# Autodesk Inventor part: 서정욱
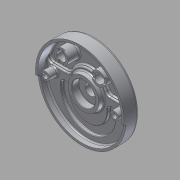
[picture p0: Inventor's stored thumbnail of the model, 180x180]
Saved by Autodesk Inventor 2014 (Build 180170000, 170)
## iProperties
Created: 2015-05
Part Number: 서정욱
Material: 알루미늄 6061
Document SubType Name: Modeling
Designer: USER
Density: 2.71 g/cm^3
Appearance: 알루미늄 - 평지
Mass: 1116.19 g
Surface Area: 1056.09 cm^2
Volume: 411.879 cm^3
Author: USER
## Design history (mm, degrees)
sketch "스케치1"
  geometry: C1 r 95 at (0, 0); 1 further point
  constraints: 1 centre point, 1 coincident
  dimensions: "d0" = 190 diameter of C1
extrude "돌출1" new body sketch "스케치1" distance "d1" = 32; taper "d2" = 0 deg
sketch "스케치2"
  geometry: L1 (0, 0)-(94.638, -8.28); L2 (-95, 0)-(95, 0); L3 (0, 0)-(-94.638, -8.28); A1 r 95 centre (0, 0) between (94.638, -8.28) and (-95, 0) reference
  constraints: 6 end point, 4 point on circle, 1 coincident, 1 horizontal, 1 midpoint
  dimensions: "d4" = 5 deg angle of L1 L2; "d5" = 5 deg angle of L3 L2
extrude "돌출2" cut sketch "스케치2" distance "d7" = 5; taper "d8" = 0 deg
sketch "스케치3"
  geometry: L1 (-89.196, 12)-(-40.249, 12); L2 (40.249, 12)-(89.196, 12); A1 r 95 centre (0, 0) between (94.638, -8.28) and (-94.638, -8.28) reference; A2 r 90 centre (0, 0) between (89.196, 12) and (-89.196, 12); A3 r 42 centre (0, 0) between (40.249, 12) and (-40.249, 12); 1 further point
  constraints: 4 end point, 4 point on circle, 2 centre point, 2 coincident, 2 horizontal
  dimensions: "d9" = 180 diameter of A2; "d10" = 84 diameter of A3; "d12" = 12 distance from line of point (0, 0) L2; "d13" = 12 distance from line of point (0, 0) L1
extrude "돌출3" cut sketch "스케치3" distance "d14" = 25; taper "d15" = 0 deg
fillet "모깎기1" dims "d16" = 10
sketch "스케치4"
  geometry: L1 (76.916, 12)-(47.117, 12) reference; L2 (-47.117, 12)-(-76.916, 12) reference; C1 r 90 at (0, 0); A1 r 10 centre (47.117, 22) between (38.056, 17.769) and (47.117, 12) reference; A2 r 42 centre (0, 0) between (38.056, 17.769) and (-38.056, 17.769) reference; A3 r 10 centre (-47.117, 22) between (-47.117, 12) and (-38.056, 17.769) reference; A4 r 10 centre (-76.916, 22) between (-86.53, 24.75) and (-76.916, 12) reference; A5 r 90 centre (0, 0) between (86.53, 24.75) and (-86.53, 24.75) reference; A6 r 10 centre (76.916, 22) between (76.916, 12) and (86.53, 24.75) reference; A7 r 95 centre (0, 0) between (94.638, -8.28) and (-94.638, -8.28) reference
  constraints: 1 centre point, 1 coincident
  dimensions: "d17" = 180 diameter of C1
extrude "돌출4" cut sketch "스케치4" distance "d18" = 18; taper "d19" = 0 deg
sketch "스케치16"
  geometry: C1 r 95 at (0, 0) reference; C2 r 25 at (0, 0)
  constraints: 1 centre point, 1 coincident
  dimensions: "d98" = 50 diameter of C2
extrude "돌출13" join sketch "스케치16" distance "d99" = 12; taper "d100" = -15 deg
sketch "스케치17"
  geometry: C1 r 35 at (0, 0); A1 r 42 centre (0, 0) between (38.056, 17.769) and (-38.056, 17.769) reference
  constraints: 1 centre point, 1 coincident
  dimensions: "d101" = 70 diameter of C1
extrude "돌출14" join sketch "스케치17" distance "d102" = 10; taper "d103" = -10 deg
hole "구멍3" diameter "d106" = 23; stored, may be unused: countersink angle "d110" = 90 deg, drill point angle "d112" = 118 deg; dims "d104" = 10, "d105" = 10, "d107" = 6, "d108" = 50, "d109" = 15, "d111" = 8
sketch "스케치18"
  geometry: C1 r 25 at (0, 0) reference; C2 r 9 at (74, 0)
  constraints: 1 centre point, 1 horizontal alignment
  dimensions: "d113" = 18 diameter of C2; "d114" = 74 distance of C1.centre C2.centre
extrude "돌출15" join sketch "스케치18" distance "d115" = 32; taper "d116" = 0 deg
hole "구멍4" sketch "스케치18" diameter "d117" = 11; stored, may be unused: countersink angle "d121" = 90 deg, drill point angle "d123" = 118 deg; dims "d118" = 6, "d119" = 18, "d120" = 11, "d122" = 8
sketch "스케치19"
  geometry: C1 r 9 at (74, 0) reference; C2 r 25 at (0, 0) reference; C3 r 15 at (40, -52)
  constraints: 1 centre point
  dimensions: "d124" = 30 diameter of C3; "d125" = 52 vertical distance of C1.centre C3.centre; "d126" = 40 horizontal distance of C2.centre C3.centre
extrude "돌출16" join sketch "스케치19" distance "d127" = 32; taper "d128" = 0 deg
hole "구멍5" diameter "d131" = 20; stored, may be unused: countersink angle "d135" = 90 deg, drill point angle "d137" = 118 deg; dims "d129" = 10, "d130" = 10, "d132" = 6, "d133" = 10, "d134" = 11, "d136" = 8
sketch "스케치20"
  geometry: L1 (-76.916, 12)-(-47.117, 12) reference; L2 (59, -19)-(41, -19); L3 (-41, -19)-(-59, -19); L4 (50, -19)-(50, -14); L5 (-50, -19)-(-50, -14); L6 (41, -19)-(41, -14); L7 (59, -19)-(59, -14); L8 (-59, -19)-(-59, -14); L9 (-41, -19)-(-41, -14); C1 r 35 at (0, 0) reference; A1 r 41 centre (0, -19) between (-41, -19) and (41, -19); A2 r 59 centre (0, -19) between (-59, -19) and (59, -19); A3 r 50 centre (0, -19) between (-50, -19) and (50, -19); A4 r 9 centre (-50, -14) between (-41, -14) and (-59, -14); A5 r 9 centre (50, -14) between (59, -14) and (41, -14); A6 r 9 centre (50, -14) between (49.84, -22.999) and (50, -23); 1 further point
  constraints: 16 end point, 15 point on circle, 7 parallel, 6 centre point, 6 tangent, 5 coincident, 2 midpoint, 2 point on line, 1 perpendicular, 1 vertical alignment
  dimensions: "d138" = 19 distance of point (0, -19) C1.centre; "d143" = 59 radius of A2; "d144" = 41 radius of A1; "d145" = 50 radius of A3; "d146" = 5 distance of L4.start L4.end; "d147" = 5 distance of L5.start L5.end; "d148" = 18 diameter of A4; "d150" = 9 radius of A5
extrude "돌출17" cut sketch "스케치20" distance "d151" = 7; taper "d152" = 0 deg
sketch "스케치21"
  geometry: L1 (0, 0)-(0, 88.845); L2 (50.912, 50.912)-(36.062, 36.062); L3 (36.062, 36.062)-(0, 0); L4 (-50.912, 50.912)-(-36.062, 36.062); L5 (-36.062, 36.062)-(0, 0); C1 r 25 at (0, 0) reference; C2 r 95 at (0, 0) reference; A1 r 72 centre (0, 0) between (50.912, 50.912) and (-50.912, 50.912); A2 r 51 centre (0, 0) between (36.062, 36.062) and (-36.062, 36.062); 1 further point
  constraints: 10 end point, 5 point on circle, 2 centre point, 2 coincident, 2 collinear, 1 vertical, 1 vertical alignment
  dimensions: "d154" = 90 deg angle of L3 L5; "d155" = 51 radius of A2; "d156" = 72 radius of A1
extrude "돌출18" join sketch "스케치21" distance "d157" = 5; taper "d158" = 0 deg
fillet "모깎기9" dims "d159" = 5
fillet "모깎기10" dims "d160" = 5
fillet "모깎기11" dims "d161" = 3
sketch "스케치22"
  geometry: C1 r 68 at (0, 0); A1 r 56 centre (0, 0) between (35.904, 42.975) and (-35.904, 42.975) reference
  constraints: 1 centre point, 1 coincident, 1 other
  dimensions: "d162" = 136 diameter of C1
feature "엠보싱2" sketch "스케치22" dims "d9" = 180, "d10" = 84, "d12" = 12, "d13" = 12, "d163" = 0.5, "d164" = 0
fillet "모깎기12" dims "d165" = 3
fillet "모깎기13" dims "d166" = 3, "d181" = 1
chamfer "모따기4" distance "d167" = 1; stored, may be unused: second distance "d168" = 2, angle "d169" = 45 deg
chamfer "모따기5" distance "d170" = 1; stored, may be unused: second distance "d171" = 2, angle "d172" = 45 deg
fillet "모깎기14" dims "d173" = 0.3
fillet "모깎기15" dims "d174" = 5
sketch "스케치23"
  geometry: L1 (-13.748, 6)-(13.748, 6); L2 (-13.748, -6)-(13.748, -6); L3 (-86, 13.748)-(-86, -13.748); L4 (-74, 13.748)-(-74, -13.748); C1 r 10 at (0, 0) reference; C2 r 10 at (-80, 0) reference; A1 r 15 centre (0, 0) between (13.748, -6) and (13.748, 6) reference; A2 r 15 centre (-80, 0) between (-74, -13.748) and (-74, 13.748) reference; 1 further point
  constraints: 8 end point, 8 point on circle, 2 parallel, 1 horizontal, 1 perpendicular
  dimensions: "d175" = 6 distance from line of L3 C2.centre; "d176" = 12 distance between parallel lines of L4 L3; "d177" = 6 distance from line of L1 C1.centre; "d178" = 12 distance between parallel lines of L2 L1
extrude "돌출19" cut sketch "스케치23" distance "d179" = 3; taper "d180" = 0 deg
chamfer "모따기6" distance "d182" = 1; stored, may be unused: second distance "d183" = 2, angle "d184" = 45 deg
node "솔리드1"
mirror "대칭1"
mirror "대칭2"
node "작업 평면1"
other parameters: "d11" = 12, "d63" = 118, "d64" = 82, "d149" = 18, "d153" = 90 deg
